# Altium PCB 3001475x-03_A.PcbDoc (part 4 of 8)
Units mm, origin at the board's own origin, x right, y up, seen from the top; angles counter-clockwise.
Board outline 100 x 72 mm, 12 copper layers (Top Layer, L2 GND, Layer 3, L4 GND, Layer 5, L6 PWR, L7 3V3, Layer 8, L9 GND, Layer 10, L11 GND, Bottom Layer), stack 1.735 mm thick; 428 components, 499 nets, 1973 pads, 1473 vias.
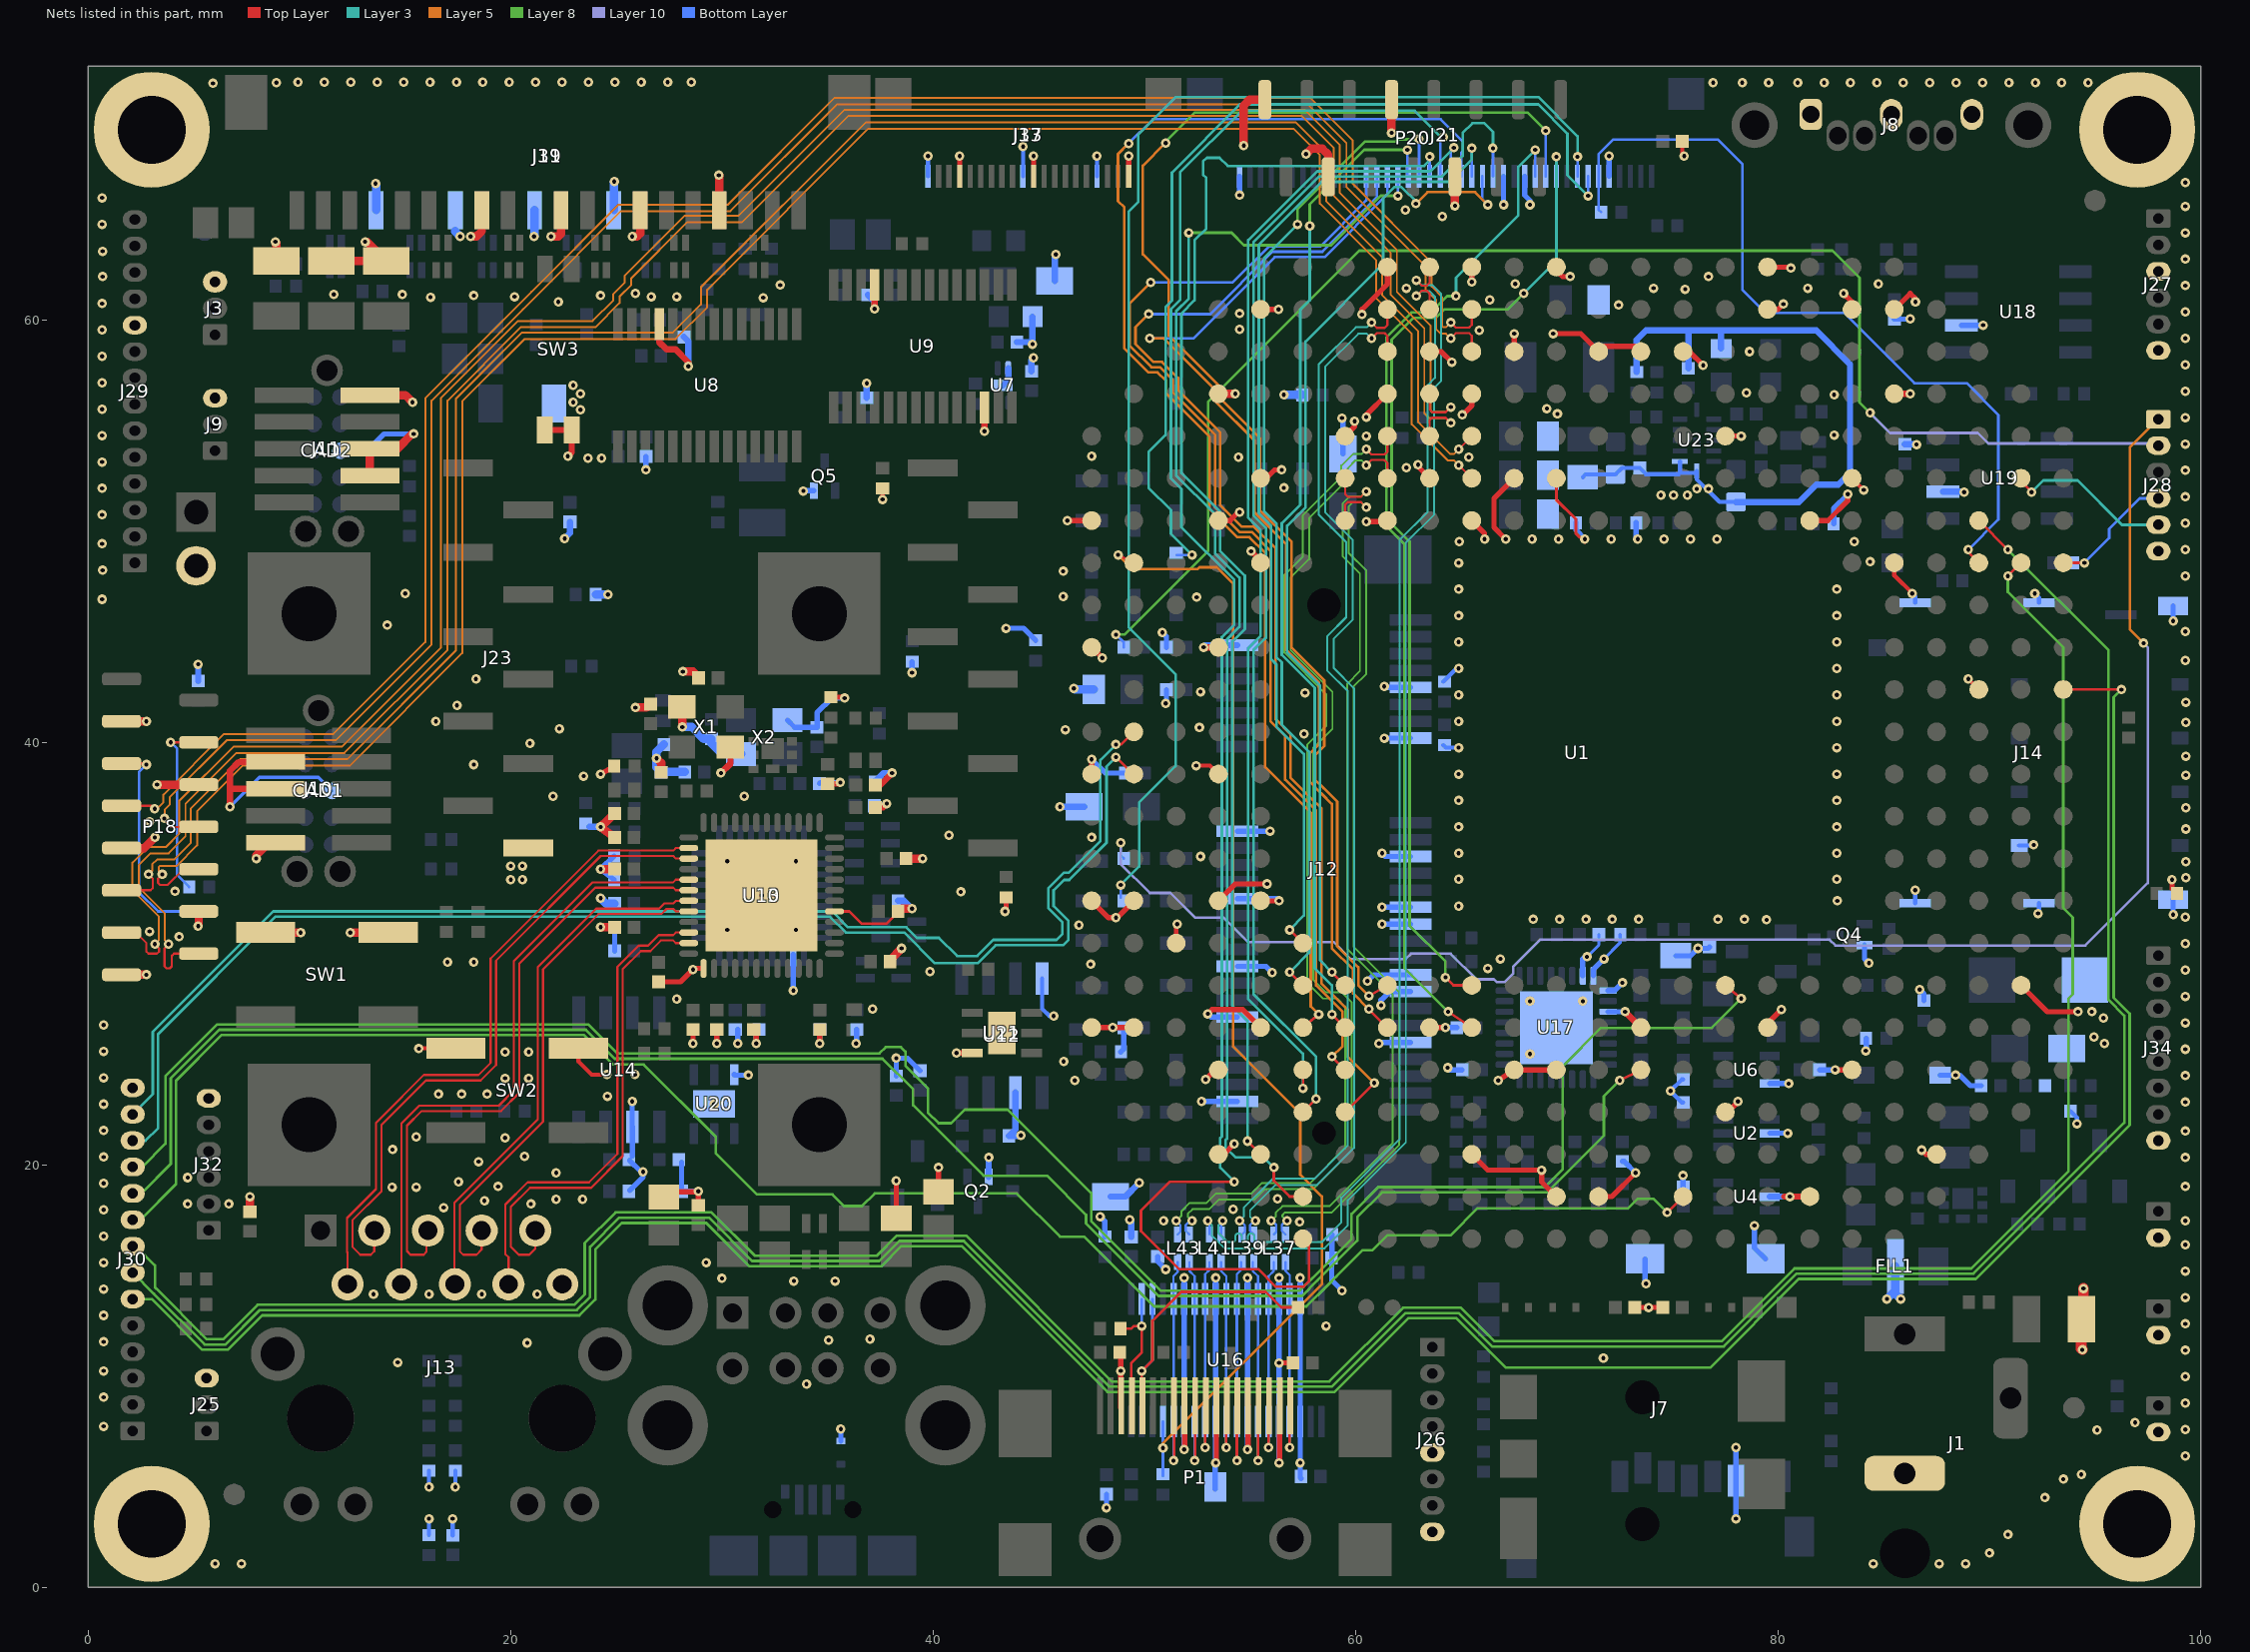
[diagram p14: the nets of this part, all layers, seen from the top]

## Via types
v1: diameter 0.45, hole 0.2, Top Layer to Bottom Layer, 1473 vias

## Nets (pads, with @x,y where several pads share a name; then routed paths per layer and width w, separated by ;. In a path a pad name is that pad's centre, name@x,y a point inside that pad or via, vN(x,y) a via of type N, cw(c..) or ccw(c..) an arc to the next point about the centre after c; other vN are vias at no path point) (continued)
DISP0_DAT11: J21.13 U1.Y7 | length 55.9
  Top Layer w0.125: v1(58.875,25.125) U1.Y7@59.5,24.5
  Layer 5 w0.125: v1(50.3,61.775) 49.3,60.775 49.3,59.454 49.3,58.785 50.322,57.763 50.728,57.763 51.337,57.153 51.337,56.57 53.337,54.57 53.337,51.126 54.501,49.963 55.074,49.963 55.963,49.074 55.963,40.996 56.663,40.296 56.663,38.236 58.061,36.837 58.07,36.837 58.125,36.782 58.125,28.5 59.375,27.25 59.375,25.625 v1(58.875,25.125)
  Bottom Layer w0.125: v1(50.3,61.775) 54.175,61.775 55.875,63.475 58.318,63.475 60.5,65.657 J21.13@60.5,66.8
DISP0_DAT12: J21.14 U1.AA7 | length 57.9
  Top Layer w0.125: U1.AA7@59.5,22.5 v1(60.875,23.875)
  Layer 5 w0.125: v1(50.2,60.275) 49.575,59.65 49.575,58.863 50.426,58.013 50.832,58.013 51.587,57.257 51.587,56.673 53.587,54.673 53.587,51.229 54.604,50.213 55.178,50.213 56.213,49.178 56.213,41.099 56.913,40.399 56.913,38.34 58.165,37.087 58.173,37.087 58.375,36.886 58.375,28.604 59.625,27.354 59.625,27.146 59.625,25.125 v1(60.875,23.875)
  Bottom Layer w0.125: v1(50.2,60.275) 53.11,60.275 56.06,63.225 58.421,63.225 61,65.804 J21.14@61,66.8
DISP0_DAT13: J21.15 U1.W8 | length 53
  Top Layer w0.125: v1(60.625,27.375) U1.W8@61.5,26.5
  Layer 5 w0.125: v1(50.25,59.125) 50.925,59.125 53.387,56.663 53.387,56.122 55.212,54.297 55.212,50.885 56.713,49.385 56.713,44.38 58.263,42.83 58.263,39.928 57.837,39.503 57.837,38.122 58.372,37.587 58.38,37.587 58.875,37.093 58.875,30.25 59.875,29.25 59.875,28.125 v1(60.625,27.375)
  Bottom Layer w0.125: v1(50.25,59.125) 52.313,59.125 56.163,62.975 58.525,62.975 61.5,65.95 J21.15@61.5,66.8
DISP0_DAT14: J21.16 U1.AC6 | length 62.1
  Top Layer w0.125: v1(56.125,19.875) 56.125,19.25 56.875,18.5 U1.AC6@57.5,18.5
  Layer 8 w0.125: v1@52.05,64.125 v1(52.1,64.125) 54.125,64.125 54.713,63.537 58.841,63.537 61.179,65.875 v1(62,65.875)
  Layer 3 w0.125: v1(52.1,64.125) 52.1,61.004 51.5,60.404 51.5,52.646 53.337,50.809 53.337,48.952 54.5,47.789 54.5,45.468 53.913,44.88 53.913,21.246 53.837,21.171 53.837,20.829 54.317,20.35 55.65,20.35 v1(56.125,19.875)
  Bottom Layer w0.125: v1(62,65.875) J21.16@62,66.8
DISP0_DAT15: J21.17 U1.W7 | length 47.7
  Top Layer w0.125: v1(58.875,27.125) U1.W7@59.5,26.5
  Layer 8 w0.125: v1(57.825,64.45) 57.825,65.475 60.4,68.05 v1(62.45,68.05)
  Layer 3 w0.125: v1(57.825,64.45) 57.825,60.925 57.375,60.475 57.375,51.25 56.5,50.375 56.5,44.146 58.063,42.584 58.063,29.312 58.875,28.5 v1(58.875,27.125)
  Bottom Layer w0.125: v1(62.45,68.05) 62.45,66.85 J21.17@62.5,66.8
DISP0_DAT16: J21.18 U1.V6 | length 47.8
  Top Layer w0.125: v1(56.875,29.125) U1.V6@57.5,28.5
  Layer 8 w0.125: v1(57.25,64.525) 57.25,65.254 60.434,68.437 61.871,68.437 61.983,68.55 v1(63,68.55)
  Layer 3 w0.125: v1(56.875,29.125) 57.8,30.05 57.8,39.55 56.5,40.85 56.5,43.793 56.25,44.043 56.25,50.357 55.663,50.945 55.663,62.938 v1(57.25,64.525)
  Bottom Layer w0.125: J21.18@63,66.8 v1(63,68.55)
DISP0_DAT17: J21.19 U1.AB5 | length 61.6
  Top Layer w0.125: v1(54.875,21.125) U1.AB5@55.5,20.5
  Layer 3 w0.125: v1(54.875,21.125) 54.875,26.825 54.163,27.537 54.163,44.777 54.75,45.364 54.75,47.893 53.587,49.055 53.587,50.913 51.75,52.75 51.75,60.3 52.375,60.925 52.375,63.775 52.925,64.325 52.925,66.725 52.775,66.875 52.775,67.498 52.952,67.675 53.55,67.675 53.937,67.288 63.238,67.288 v1@63.5,67.55
  Bottom Layer w0.125: J21.19@63.5,66.8 v1(63.5,67.725)
DISP0_DAT18: J21.20 U1.AD6 | length 83.1
  Top Layer w0.125: v1(54.25,19.2) 51.2,19.2 49.837,17.837 49.837,16.863 51.637,15.063 55.379,15.063 56.204,14.237 57.546,14.237 57.788,14.479 57.788,16.212 U1.AD6@57.5,16.5
  Layer 3 w0.125: v1(54.25,19.2) 53.587,19.863 53.587,21.274 53.663,21.349 53.663,44.984 54.25,45.571 54.25,47.686 51.75,50.186 51.75,52 51.25,52.5 51.25,60.507 51.688,60.945 51.688,66.988 54.6,69.9 62.8,69.9 64.05,68.65 v1(64.15,68.65)
  Bottom Layer w0.125: J21.20@64,66.8 64,68.5 v1(64.15,68.65)
DISP0_DAT19: J21.21 U1.Y6 | length 55.5
  Top Layer w0.125: v1(57.5,23.625) U1.Y6@57.5,24.5
  Layer 3 w0.125: v1(57.5,23.625) 57.5,25.261 54.913,27.848 54.913,44.466 55.5,45.054 55.5,50.046 54.913,50.634 54.913,63.77 58.18,67.038 63.538,67.038 v1(64.65,68.15)
  Bottom Layer w0.125: J21.21@64.5,66.8 64.5,68 v1(64.65,68.15)
DISP0_DAT20: J21.22 U1.W6 | length 65.3
  Top Layer w0.125: U1.W6@57.5,26.5 v1(58.25,27.125)
  Layer 5 w0.125: v1(49.25,68.35) 48.75,67.85 48.75,65.625 49.05,65.325 49.05,58.65 50.187,57.513 50.624,57.513 51.013,57.124 51.013,56.541 53.087,54.466 53.087,51.022 54.397,49.713 54.971,49.713 55.713,48.971 55.713,38.833 57.875,36.67 57.875,27.5 v1(58.25,27.125)
  Bottom Layer w0.125: v1(49.25,68.35) 50.4,69.5 64.025,69.5 65.063,68.462 65.063,67.979 65,67.917 65,67.725 J21.22@65,66.8
DISP0_DAT21: J21.23 U1.U6 | length 48.1
  Top Layer w0.125: v1(56.875,31.125) U1.U6@57.5,30.5
  Layer 3 w0.125: v1(56.875,31.125) 57.55,31.8 57.55,39.446 56.25,40.746 56.25,43.689 56,43.939 56,50.254 55.413,50.841 55.413,63.563 58.388,66.538 64.438,66.538 65.5,67.6 v1(65.5,68.125)
  Bottom Layer w0.125: J21.23@65.5,66.8 v1(65.5,68.125)
DISP0_DAT22: J21.24 U1.V7 | length 47.8
  Top Layer w0.125: v1(58.875,29.125) U1.V7@59.5,28.5
  Layer 5 w0.125: v1(62.85,65.5) 63.4,66.05 65.65,66.05 v1(66.25,65.45)
  Layer 3 w0.125: v1(58.875,29.125) 58.313,29.687 58.313,42.687 56.75,44.25 56.75,50.25 57.625,51.125 57.625,58.975 61.3,62.65 61.3,65.758 61.829,66.288 62.171,66.288 62.85,65.608 v1(62.85,65.5)
  Bottom Layer w0.125: J21.24@66,66.8 66,65.7 v1(66.25,65.45)
DISP0_DAT23: J21.25 U1.AA6 | length 59.7
  Top Layer w0.125: U1.AA6@57.5,22.5 v1(58.125,23.125)
  Layer 3 w0.125: v1(58.125,23.125) 58.125,25.125 55.163,28.087 55.163,44.363 55.75,44.95 55.75,50.15 55.163,50.737 55.163,63.666 58.284,66.788 64.088,66.788 65.063,67.763 65.063,68.846 65.529,69.313 66.087,69.313 66.5,68.9 v1(66.5,68.125)
  Bottom Layer w0.125: J21.25@66.5,66.8 v1(66.5,68.125)
DISP0_DRDY: J21.31 U1.V10 | length 47.8
  Top Layer w0.125: v1(64.25,28.875) 64.625,28.5 U1.V10@65.5,28.5
  Layer 8 w0.125: v1(64.25,28.875) 64.25,29.625 62.55,31.325 62.55,49.5 61.7,50.35 61.7,59.058 62.742,60.1 63.8,60.1 64.2,60.5 67.2,60.5 v1(67.95,61.25)
  Layer 3 w0.125: v1(67.95,61.25) 69.5,62.8 v1(69.5,67.725)
  Bottom Layer w0.125: J21.31@69.5,66.8 v1(69.5,67.725)
DISP0_HSYNC: J21.29 U1.W10 | length 48.3
  Top Layer w0.125: v1(64.375,27.25) U1.W10@65.5,26.5
  Layer 8 w0.125: v1(64.375,27.25) 62.3,29.325 62.3,49.396 61.45,50.246 61.45,59.162 62.638,60.35 63.55,60.35 64.325,61.125 v1(64.75,61.125)
  Layer 3 w0.125: v1(64.75,61.125) 64.75,62 67.7,64.95 67.7,67.25 v1(68.5,68.05)
  Bottom Layer w0.125: J21.29@68.5,66.8 v1(68.5,68.05)
DISP0_I2C_SCL: J21.33 R103.2 | length 62.5
  Layer 3 w0.125: v1(48.875,33.25) 49.75,34.125 49.75,37.15 51.475,38.875 51.475,43.225 49.25,45.45 49.25,65.125 49.7,65.575 49.7,68.75 51.5,70.55 68.646,70.55 70.5,68.696 v1(70.5,67.725)
  Bottom Layer w0.125: R103.2@48.875,32.645 v1(48.875,33.25) ; J21.33@70.5,66.8 v1(70.5,67.725)
DISP0_I2C_SDA: J21.34 R105.2 | length 45
  Layer 3 w0.125: v1(52.25,48.875) 51.25,49.875 51.25,51 50.2,52.05 50.2,53.75 51,54.55 51,60.611 51.298,60.909 51.298,66.973 54.525,70.2 68.643,70.2 70.025,68.818 70.025,66.85 v1(71,65.875)
  Bottom Layer w0.125: R105.2@51.52,48.875 v1(52.25,48.875) ; v1(71,65.875) J21.34@71,66.8
DISP0_IRQ_N: J21.35 R78.2 U1.H22 | length 38.7
  Top Layer w0.125: v1(89,49.125) 89,49 U1.H22@89.5,48.5
  Bottom Layer w0.125: R78.2@71.62,65.1 71.5,65.22 J21.35@71.5,66.8 71.5,67.833 72.204,68.538 77.143,68.538 78.315,67.366 78.315,61.413 79.391,60.337 83.113,60.337 86.45,57 88.925,57 90.425,55.5 90.425,50.55 v1(89,49.125)
DISP0_VSYNC: J21.30 U1.V8 | length 67.7
  Top Layer w0.125: v1(60.625,28) U1.V8@61.5,28.5
  Layer 8 w0.125: v1@51,68.425 52.388,69.813 68.137,69.813 v1(69,68.95)
  Layer 5 w0.125: v1(51,68.375) 49.925,67.3 49.925,63.1 51.15,61.875 51.15,59.254 53.637,56.766 53.637,56.226 55.462,54.401 55.462,50.989 56.963,49.489 56.963,44.484 58.513,42.934 58.513,39.824 58.087,39.399 58.087,38.226 58.476,37.837 58.484,37.837 59.125,37.196 59.125,30.354 60.125,29.354 60.125,29.146 60.125,28.5 v1(60.625,28)
  Bottom Layer w0.125: J21.30@69,66.8 v1(69,68.95)
DSI_CLK0_N: P18.11 U1.E10 | length 100
  Top Layer w0.104: P18.11@1.575,33 2.95,33 3.048,33.098 3.048,33.553 v1(2.851,33.75) ; v1(64.875,53.875) U1.E10@65.5,54.5
  Layer 5 w0.093: v1(2.851,33.75) 3.026,33.925 3.026,34.224 3.251,34.45 4.05,34.45 4.85,35.25 4.85,36.874 7.176,39.2 12.25,39.2 17.4,44.35 17.4,56.262 20.538,59.4 27.675,59.4 29,60.725 29,61.55 36.8,69.35 57.174,69.35 58.6,67.924 58.6,65.624 61.263,62.961 61.263,61.161 62.95,59.474 62.95,59.316 62.951,58.735 62.95,55.174 64.474,53.65 64.65,53.65 v1(64.875,53.875)
DSI_CLK0_P: P18.10 U1.F10 | length 100
  Top Layer w0.104: v1(3.5,33.75) 3.303,33.553 3.303,33.347 3.4,33.25 3.75,33.25 4.5,34 P18.10@5.225,34 ; v1(64.875,53.125) U1.F10@65.5,52.5
  Layer 5 w0.093: v1(3.5,33.75) 3.326,33.925 3.326,34.1 3.375,34.15 4.174,34.15 5.15,35.126 5.15,36.75 7.3,38.9 12.374,38.9 17.7,44.226 17.7,56.138 20.662,59.1 27.799,59.1 29.3,60.601 29.3,61.426 36.924,69.05 57.05,69.05 58.3,67.8 58.3,65.5 60.963,62.837 60.963,61.037 62.65,59.35 62.65,59.191 62.651,58.859 ; 62.65,58.859 62.65,55.05 64.35,53.35 64.65,53.35 v1(64.875,53.125)
DSI_D0_N: P18.8 U1.C10 | length 93.1
  Top Layer w0.104: v1(3.6,36.4) 3.6,36.3 3.9,36 P18.8@5.225,36 ; v1(64.5,59.125) 64.744,59.369 65.381,59.369 65.5,59.25 U1.C10@65.5,58.5
  Layer 5 w0.093: v1(3.6,36.4) 3.616,36.416 3.616,36.813 3.85,37.048 3.85,37.4 6.55,40.1 11.724,40.1 16.25,44.626 16.25,56.176 20.573,60.499 21.101,61.027 25.224,65.15 30.4,65.15 35.462,70.212 57.714,70.212 59.562,68.364 59.562,66.288 63.3,62.55 63.3,61.45 63.8,60.95 63.8,59.576 64.026,59.35 64.275,59.35 v1(64.5,59.125)
DSI_D0_P: P18.7 U1.B10 | length 93.1
  Top Layer w0.104: P18.7@1.575,37 3,37 v1(3.141,36.859) ; v1(64.5,59.875) 64.744,59.631 65.365,59.631 65.5,59.766 U1.B10@65.5,60.5
  Layer 5 w0.093: v1(3.141,36.859) 3.157,36.875 3.316,36.875 3.316,36.938 3.55,37.172 3.55,37.524 6.426,40.4 11.6,40.4 15.95,44.75 15.95,56.3 20.273,60.623 20.977,61.327 25.1,65.45 30.276,65.45 35.338,70.512 57.838,70.512 59.862,68.488 59.862,66.443 63.6,62.705 63.6,61.574 64.1,61.074 64.1,59.7 64.15,59.65 64.275,59.65 v1(64.5,59.875)
DSI_D1_N: P18.14 U1.E9 | length 105.5
  Top Layer w0.104: v1(3.799,30.45) 3.602,30.253 3.602,29.398 3.7,29.3 3.85,29.3 3.95,29.4 3.95,29.9 4.05,30 4.3,30 P18.14@5.225,30 ; U1.E9@63.5,54.5 63.5,55.25 63.619,55.369 64.256,55.369 v1(64.5,55.125)
  Layer 5 w0.093: v1(3.799,30.45) 3.625,30.625 3.625,31.9 2.388,33.136 2.388,34.188 2.95,34.75 3.55,34.75 3.799,34.75 4.6,35.551 4.6,37.1 7,39.5 12.124,39.5 17,44.376 17,56.182 20.468,59.65 24,59.65 25.15,60.8 25.15,61.1 25.7,61.65 25.7,61.976 28.348,64.624 30.949,64.624 35.975,69.65 57.45,69.65 58.95,68.15 58.95,65.884 61.65,63.184 61.65,61.2 63.25,59.6 63.25,55.576 63.476,55.35 64.275,55.35 v1(64.5,55.125)
DSI_D1_P: P18.13 U1.D9 | length 105.5
  Top Layer w0.104: P18.13@1.575,31 2.25,31 2.75,30.5 2.75,30.1 2.85,30 3.247,30 3.347,30.1 3.347,30.253 v1(3.15,30.45) ; U1.D9@63.5,56.5 63.5,55.766 63.635,55.631 64.256,55.631 v1(64.5,55.875)
  Layer 5 w0.093: v1(3.15,30.45) 3.325,30.625 3.325,31.775 2.088,33.012 2.088,34.312 2.826,35.05 3.674,35.05 4.3,35.676 4.3,37.224 6.876,39.8 12,39.8 16.7,44.5 16.7,56.306 20.344,59.95 23.876,59.95 24.85,60.924 24.85,61.224 25.4,61.774 25.4,62.1 28.224,64.924 30.774,64.924 35.8,69.95 57.574,69.95 59.25,68.274 59.25,66.008 61.95,63.308 61.95,61.324 63.55,59.724 63.55,55.7 63.6,55.65 64.275,55.65 v1(64.5,55.875)
DSI_I2C_SCL: P18.5 R155.2 | length 10.1
  Top Layer w0.125: P18.5@1.575,39 2.7,39 v1(2.75,38.95)
  Bottom Layer w0.125: v1(2.75,38.95) 2.4,38.6 2.4,32.9 3.3,32 R155.2@4.745,32
DSI_I2C_SDA: P18.4 R156.2 | length 8.5
  Top Layer w0.125: v1(3.9,40) P18.4@5.225,40
  Bottom Layer w0.125: v1(3.9,40) 4.2,39.7 4.2,33.72 R156.2@4.77,33.15
ETH_TXRXA_N: J13.3 U10.3 | length 31.3
  Top Layer w0.104: J13.3@13.54,16.89 13.54,15.915 13.375,15.75 12.875,15.75 12.5,16.125 12.5,17.375 13.875,18.75 13.875,21.889 15.986,24.001 18.576,24.001 19.3,24.725 19.3,29.664 24.258,34.622 27.689,34.622 27.811,34.5 U10.3@28.425,34.5
ETH_TXRXA_P: J13.2 U10.2 | length 31.3
  Top Layer w0.104: J13.2@12.27,14.35 12.27,15.855 12.245,15.88 12.245,17.481 13.62,18.856 13.62,21.995 13.907,22.282 15.881,24.256 18.47,24.256 19.045,24.831 19.045,29.77 24.152,34.877 27.689,34.877 27.811,35 U10.2@28.425,35
ETH_TXRXB_N: J13.5 U10.6 | length 29.6
  Top Layer w0.104: J13.5@16,16.81 16,15.875 15.875,15.75 15.25,15.75 15.08,15.92 15.08,21.855 15.775,22.55 19.536,22.55 20.4,23.414 20.4,29.525 23.997,33.122 27.689,33.122 27.811,33 U10.6@28.425,33
ETH_TXRXB_P: J13.4 U10.5 | length 29.6
  Top Layer w0.104: J13.4@14.825,14.365 14.825,21.961 15.669,22.805 19.43,22.805 20.145,23.52 20.145,29.645 23.877,33.377 27.689,33.377 27.811,33.5 U10.5@28.425,33.5
ETH_TXRXC_N: J13.7 U10.8 | length 25.2
  Top Layer w0.104: J13.7@18.62,16.89 18.62,15.995 18.375,15.75 17.75,15.75 17.583,15.917 17.583,18.097 21.53,22.044 21.53,29.255 24.15,31.875 27.128,31.875 27.375,32.123 27.689,32.123 27.811,32 U10.8@28.425,32
ETH_TXRXC_P: J13.6 U10.7 | length 25.2
  Top Layer w0.104: U10.7@28.425,32.5 27.811,32.5 27.689,32.378 27.269,32.378 27.022,32.13 24.23,32.13 24.044,32.13 21.275,29.361 21.275,22.15 17.328,18.203 J13.6@17.328,14.372 ; J13.6@17.328,14.372 J13.6@17.35,14.35 ; J13.6@17.328,14.372 J13.6@17.35,14.35 ; J13.6@17.35,14.35 17.375,14.375 J13.6@17.35,14.35
ETH_TXRXD_N: J13.9 U10.11 | length 23.1
  Top Layer w0.104: J13.9@21.16,16.89 21.16,16.035 20.875,15.75 20.375,15.75 20,16.125 20,18.014 20.905,18.92 23.805,18.92 25.3,20.414 25.3,29.269 26.156,30.125 26.611,30.125 27.108,30.622 27.689,30.622 27.811,30.5 U10.11@28.425,30.5
ETH_TXRXD_P: J13.8 U10.10 | length 23
  Top Layer w0.104: J13.8@19.89,14.35 19.89,15.624 19.745,15.769 19.745,18.12 20.8,19.175 23.7,19.175 25.045,20.52 25.045,29.375 25.05,29.38 26.05,30.38 26.505,30.38 27.002,30.877 27.689,30.877 27.811,31 U10.10@28.425,31
EXP_GPIO_0: J30.6 U1.L24 | length 134.5
  Top Layer w0.125: U1.L24@93.5,42.5 v1(96.25,42.5)
  Layer 8 w0.125: J30.6@2.1,13.65 3,13.65 5.4,11.25 6.6,11.25 8.225,12.875 23.25,12.875 24,13.625 24,16 25.25,17.25 29.25,17.25 29.3,17.2 29.304,17.2 31.304,15.2 37.546,15.2 38.496,16.15 41.343,16.15 48.243,9.25 48.729,9.25 59,9.25 62.487,12.737 64.77,12.737 67.107,10.4 76.775,10.4 80.975,14.6 89.35,14.6 96.64,21.89 96.64,27.164 95.887,27.916 95.887,42.137 v1(96.25,42.5)
EXP_GPIO_1: J30.7 U1.G22 | length 141.5
  Top Layer w0.125: U1.G22@89.5,50.5 v1(90.875,49.125)
  Layer 8 w0.125: J30.7@2.1,14.9 3.1,13.9 3.104,13.9 5.504,11.5 6.496,11.5 8.121,13.125 23.125,13.125 23.75,13.75 23.75,16.125 25.125,17.5 29.375,17.5 31.425,15.45 37.443,15.45 38.393,16.4 41.446,16.4 48.346,9.5 58.875,9.5 62.362,12.987 64.873,12.987 66.461,11.4 77.421,11.4 80.871,14.85 89.246,14.85 96.39,21.993 96.39,27.06 95.637,27.813 95.637,44.363 v1(90.875,49.125)
EXP_GPIO_2: J30.8 U1.H23 | length 137.9
  Top Layer w0.125: v1(90.875,47.875) U1.H23@91.5,48.5
  Layer 8 w0.125: J30.8@2.1,16.15 2.25,16.15 3.15,15.25 3.15,14.204 3.204,14.15 3.207,14.15 5.607,11.75 6.393,11.75 8.018,13.375 23,13.375 23.5,13.875 23.5,16.293 24.957,17.75 29.5,17.75 31.55,15.7 37.325,15.7 38.275,16.65 41.55,16.65 48.45,9.75 58.75,9.75 62.237,13.237 64.977,13.237 66.564,11.65 77.318,11.65 80.768,15.1 89.143,15.1 93.737,19.695 93.737,27.862 93.95,28.075 93.95,31.717 93.5,32.167 93.5,44.5 90.875,47.125 v1(90.875,47.875)
EXP_GPIO_3: J30.9 U1.AC15 | length 88.9
  Top Layer w0.125: v1(74.75,17.75) U1.AC15@75.5,18.5
  Layer 8 w0.125: J30.9@2.1,17.4 2.45,17.4 4.15,19.1 4.15,23.993 6.307,26.15 23.45,26.15 24.85,24.75 26.3,24.75 29.7,21.35 29.7,20.55 31.65,18.6 35.23,18.6 35.78,18.05 36.625,18.05 37.225,18.65 43.954,18.65 46.004,16.6 47.15,16.6 50.45,13.3 51.039,13.3 57.669,13.3 58.687,14.318 58.687,14.324 59.076,14.713 59.082,14.713 60.332,15.962 60.796,15.962 61.508,16.675 64.504,16.675 65.779,17.95 72.904,17.95 73.354,18.4 74.1,18.4 v1(74.75,17.75)
EXP_GPIO_4: J30.10 U1.Y14 | length 89
  Top Layer w0.125: v1(72.5,24) U1.Y14@73.5,24.5
  Layer 8 w0.125: J30.10@2.1,18.65 2.5,18.65 3.9,20.05 3.9,24.096 6.204,26.4 23.554,26.4 24.929,25.025 37.6,25.025 39.05,23.575 39.05,22.825 42.388,19.487 45.388,19.487 47.237,17.638 47.237,17.226 50.663,13.8 57.462,13.8 58.187,14.526 58.187,14.532 58.868,15.213 58.874,15.213 60.075,16.413 60.075,17.533 61.242,18.7 69.054,18.7 71.75,21.396 71.75,23.25 v1(72.5,24)
EXP_GPIO_5: J30.11 U1.V16 | length 98.9
  Top Layer w0.125: U1.V16@77.5,28.5 v1(78.25,27.875)
  Layer 8 w0.125: J30.11@2.1,19.9 2.55,19.9 3.65,21 3.65,24.2 6.1,26.65 23.657,26.65 25.032,25.275 37.45,25.275 37.75,25.575 38.475,25.575 38.685,25.365 38.685,24.69 39.75,23.625 39.75,22.479 40.25,21.979 40.854,21.979 41.488,22.613 43.521,22.613 47.487,18.646 47.487,17.329 50.767,14.05 57.358,14.05 57.937,14.629 57.937,14.635 58.765,15.463 58.771,15.463 59.8,16.492 59.8,17.675 61.075,18.95 68.95,18.95 69.8,19.8 69.8,24.675 71.612,26.487 76.862,26.487 v1(78.25,27.875)
EXP_GPIO_6: J30.12 U1.N2 | length 64.2
  Top Layer w0.125: v1(48.65,39.3) 49.45,38.5 U1.N2@49.5,38.5
  Layer 3 w0.125: J30.12@2.1,21.15 2.7,21.15 3.3,21.75 3.3,26.196 8.854,31.75 35.113,31.75 35.863,31 38.625,31 40.075,29.55 42.1,29.55 42.95,30.4 46.154,30.4 46.4,30.646 46.4,31.55 45.7,32.25 45.7,32.996 46.191,33.488 46.438,33.488 48.2,35.25 48.2,38.85 v1(48.65,39.3)
EXP_GPIO_7: J30.13 U1.M2 | length 62.8
  Top Layer w0.125: v1(48.65,39.9) 48.9,39.9 U1.M2@49.5,40.5
  Layer 3 w0.125: J30.13@2.1,22.4 3.05,23.35 3.05,26.3 8.75,32 35.216,32 35.966,31.25 38.729,31.25 39.229,30.75 40.267,30.75 41.129,29.887 42.084,29.887 42.846,30.65 45.833,30.65 46.113,30.929 46.113,31.484 45.45,32.146 45.45,33.1 46.187,33.837 46.421,33.837 47.913,35.329 47.913,39.163 v1(48.65,39.9)
EXP_I2C_GPIO: J28.5 U1.F23 | length 8
  Top Layer w0.125: U1.F23@91.5,52.5 91.5,52.35 v1(92,51.85)
  Layer 3 w0.125: v1(92,51.85) 92.55,52.4 94.175,52.4 96.275,50.3 J28.5@98,50.3
EXP_I2C_IRQ_N: J28.4 R117.2 U1.H24 | length 6.5
  Top Layer w0.125: U1.H24@93.5,48.5 v1(94.5,48.5)
  Bottom Layer w0.125: R117.2@93.98,48.5 v1(94.5,48.5) 95.675,49.675 95.675,50.1 97.125,51.55 J28.4@98,51.55
EXP_I2C_SCL: J28.1 R106.2 | length 78.2
  Layer 5 w0.125: v1(97.3,44.7) 96.65,45.35 96.65,53.95 J28.1@98,55.3
  Layer 10 w0.125: v1(48.875,35.25) 48.875,34.25 50.25,32.875 51.225,32.875 52.4,31.7 53.75,31.7 54.9,30.55 58.95,30.55 59.75,29.75 62.375,29.75 62.625,30 64.5,30 65.713,28.788 66.546,28.788 66.683,28.65 67.05,28.65 67.45,29.05 67.45,29.383 68.729,30.663 82.437,30.663 82.713,30.387 94.537,30.387 97.5,33.35 97.5,44.5 v1(97.3,44.7)
  Bottom Layer w0.125: v1(48.875,35.25) 48.875,34.645 R106.2@49.02,34.5
EXP_I2C_SDA: J28.2 R107.2 | length 69
  Layer 8 w0.125: v1(48.65,45.1) 49.058,45.1 53.012,49.054 53.012,56.112 60.174,63.274 82.576,63.274 83.85,62 83.85,56.1 v1(84.35,55.6)
  Layer 10 w0.125: v1(84.35,55.6) 85.3,54.65 89.45,54.65 89.95,54.15 97.9,54.15 J28.2@98,54.05
  Bottom Layer w0.125: v1(48.65,45.1) 49.02,44.73 R107.2@49.02,44.5
GND: C1.2 C2.1 C3.1 C4.1 C5.1 C6.1 C7.1 C8.1 C9.2 C10.1 C11.1 C12.1 C13.1 C24.1 C25.1 C26.1 C27.1 C28.1 C29.1 C30.1 C33.2 C34.2 C35.2 C36.2 C37.1 C38.1 C39.1 C40.1 C41.1 C42.1 C43.1 C44.1 C45.1 C46.1 C47.1 C48.1 C49.1 C50.1 C51.1 C52.1 C53.1 C54.1 C55.1 C56.1 C57.1 C58.1 C59.1 C60.1 C61.1 C62.1 C63.2 C64.2 C65.2 C66.1 C67.1 C68.1 C69.1 C70.1 C71.1 C72.1 C73.1 C74.1 C75.1 C76.1 C77.1 C78.1 C79.1 C80.1 C81.1 C82.1 C83.1 C84.1 C85.1 C86.1 C89.1 C90.1 C95.1 C96.1 C99.1 C100.1 C101.1 C105.1 C106.1 C109.1 C110.1 C111.1 C112.1 C113.1 C114.1 C115.1 C116.1 C117.1 C118.1 C119.1 CAD1.3 CAD2.3 D1.K D2.A D4.K D5.K D6.K D10.1 FIL1.2 J1.2 J2.2 J3.3 J4.2 J5.2 J7.6 J7.9 J7.10 J8.1 J8.4 J8.7 J9.3 J10.3 J10.5 J10.9 J11.3 J11.5 J11.9 J12.4 J12.9 J12.15 J12.18 J12.21 J12.26 J12.27 J12.29 J12.34 J12.35 J12.37 J12.40 J12.43 J12.50 J13.10 J14.5 J14.11 J14.12 J14.13 J14.14 J14.15 J14.16 J17.1 J17.10 J17.17 J18.2 J19.4 J19.7 J19.10 J19.13 J21.1 J21.26 J21.28 J21.36 J23.10 J25.3 J26.5 J26.8 J27.3 J27.6 J28.6 J29.10 J30.14 J31.4 J31.7 J31.10 J31.13 J32.6 J33.1 J33.10 J33.17 J34.8 L12.1 L13.1 L15.1 L27.1 P1.2 P1.5 P1.8 P1.11 P1.17 P18.3 P18.6 P18.9 P18.12 P18.15 P20.6 P20.9 P20.12 P20.15 pad.0@3,3 pad.0@3,69 pad.0@97,3 pad.0@97,69 Q2.S Q4.S Q5.S R5.1 R14.1 R17.2 R18.2 R19.2 R20.1 R27.1 R28.2 R29.2 R37.1 R42.1 R43.1 R46.1 R49.1 R50.1 R54.2 R56.2 R57.2 R59.2 R70.1 R71.1 R73.1 R74.1 R84.1 R89.1 R130.2 R134.2 R136.2 R138.1 R144.1 R145.1 R146.1 SW1.1 SW1.2 SW2.1 SW2.2 SW3.1 SW3.2 U1.A8 U1.A10 U1.A12 U1.A17 U1.AA16 U1.AB4 U1.AB10 U1.AB21 U1.AC12 U1.AC13 U1.AC18 U1.B5 U1.B17 U1.B19 U1.B20 U1.C9 U1.C11 U1.C13 U1.C14 U1.C15 U1.D4 U1.D8 U1.D10 U1.D20 U1.E7 U1.E16 U1.F5 U1.F9 U1.F11 U1.F12 U1.F19 U1.G1 U1.G4 U1.G8 U1.G10 U1.G18 U1.H5 U1.H20 U1.K1 U1.K4 U1.L22 U1.N1 U1.N4 U1.T1 U1.T2 U1.T4 U1.T5 U1.U3 U1.V23 U1.W1 U1.W2 U1.W5 U1.W9 U1.W14 U1.W17 U1.Y4 U1.Y11 U1.Y12 U1.Y19 U2.2 U4.2 U5.A U6.3 U7.2 U7.5 U8.25 U9.12 U9.25 U10.13 U10.29 U10.49 U12.4 U12.6 U13.11 U13.37 U14.6 U16.3 U16.5 U16.8 U16.11 U16.14 U16.25 U16.28 U16.31 U16.34 U16.36 U17.1 U17.3 U17.31 U17.32 U17.33 U18.2 U19.2 U20.3 U20.7 U21.3 U21.7 U23.1 U23.12 X1.2 X1.4 X2.2 X2.4 | length 425.4
  Top Layer w0.125: U10.29@35.325,32 36.021,32 36.609,31.413 37.788,31.413 C54.1@38.5,32.125
  Top Layer w0.15: U1.F12@69.5,52.5 69.5,51.5 70.42,50.58 70.42,49.905 v1@70.85,49.475
  Top Layer w0.2: v1(15.65,25.5) 15.675,25.525 SW2.1@17.4,25.525 ; SW2.2@23.2,25.525 23.2,24.9 23.825,24.275 v1(24.55,24.275) ; v1(37.6,51.5) R136.2@37.6,52.02 ; U1.U3@51.5,30.5 51.5,31.35 v1(51.55,31.4) ; v1(52.45,38.9) 53.1,38.9 U1.N4@53.5,38.5 ; C106.1@75.46,68.45 75.46,67.84 v1(75.55,67.75) ; U1.F19@83.5,52.5 v1(84.05,51.95) ; U1.H20@85.5,48.5 85.5,47.9 v1(86.35,47.05) ; v1(89,43) U1.L22@89.5,42.5
  Top Layer w0.25: v1(24.25,38.5) R49.1@24.895,38.875 ; R49.1@24.834,38.953 R49.1@24.895,39 ; C43.1@27,28.665 28.04,28.665 v1(28.625,29.25) 28.675,29.3 U10.13@29.125,29.3 ; L15.1@27.25,18.725 v1@28.85,18.725 ; v1(28.625,25.75) C50.1@28.625,26.415 ; C71.1@28.875,18.085 v1@28.875,18.725 ; v1(29.75,25.75) C46.1@29.75,26.415 ; v1(31.625,25.75) C51.1@31.625,26.415 ; v1(34.625,25.75) C52.1@34.625,26.415 ; C47.1@35,38.04 35.54,38.04 v1(35.6,38.1) ; R50.1@35.15,42.14 35.76,42.14 v1(35.8,42.1) ; L13.1@38.25,17.475 v1(38.25,19.25) ; L12.1@40.25,18.725 v1(40.25,19.875) ; v1(41.1,25.3) U21.3@41.85,25.3 ; J17.17@41.25,66.8 v1(41.25,67.75) ; v1(43.4,32) 43.45,32.05 R130.2@43.45,32.67 ; J17.10@44.75,66.8 v1(44.75,67.75) ; v1(46.35,50.5) U1.G1@47.5,50.5 ; U1.W1@47.5,26.5 U1.W2@49.5,26.5 ; U1.T1@47.5,32.5 48.3,31.7 v1(48.65,31.7) 48.7,31.7 U1.T2@49.5,32.5 ; U1.N1@47.5,38.5 v1(47.5,39.2) ; U1.K1@47.5,44.5 v1(48,44) ; P1.17@48.875,8.5 v1(48.875,10.25) C86.1@48.875,11.085 ; J17.1@49.25,66.8 v1(49.25,67.75) ; v1(51.875,6.525) 51.9,6.55 P1.11@51.9,8.6 ; v1(52.9,24.05) 53.35,24.5 U1.Y4@53.5,24.5 ; v1(53,27.15) 53.2,27.35 54.65,27.35 U1.W5@55.5,26.5 ; v1(53.375,5.9) 53.4,5.925 P1.8@53.4,8.6 ; U1.AB4@53.5,20.5 53.75,20.5 v1(54.25,21) ; U1.T4@53.5,32.5 54.3,33.3 v1(55.8,33.3) ; U1.G4@53.5,50.5 54.05,50.5 54.45,50.9 v1(54.5,50.9) ; v1(54.875,6.525) 54.9,6.55 P1.5@54.9,8.6 ; v1(55.05,49.05) 55.5,48.6 U1.H5@55.5,48.5 ; U1.T5@55.5,32.5 v1(56.375,32.5) ; U1.F5@55.5,52.5 55.758,52.5 56.158,52.9 v1(56.5,52.9) ; U1.B5@55.5,60.5 v1(56.35,60.5) ; v1(56.375,5.9) 56.4,5.925 P1.2@56.4,8.6 ; v1(56.375,10.625) C82.1@57.04,10.625 ; U1.E7@59.5,54.5 59.95,54.95 v1(59.95,55.2) ; v1(60.3,60.25) 60.3,60.5 61.5,61.7 U1.A8@61.5,62.5 ; v1(60.5,50.45) 61.45,50.45 U1.G8@61.5,50.5 ; v1(60.5,55.4) 60.5,55.5 U1.D8@61.5,56.5 ; v1(62.95,53.15) 62.95,53.05 U1.F9@63.5,52.5 ; U1.W9@63.5,26.5 v1(64.25,26.5) ; U1.C9@63.5,58.5 64.05,58.5 v1(64.55,58) ; v1(65.05,55.5) 65.5,55.95 U1.D10@65.5,56.5 ; U1.AB10@65.5,20.5 66.25,19.75 v1(68.8,19.75) 68.8,19.2 U1.AC12@69.5,18.5 ; U1.G10@65.5,50.5 66.1,49.9 v1(66.1,49.625) v1@66.1,49.6 ; v1(65.5,61.8) U1.A10@65.5,62.5 ; v1(66.75,24) U1.Y11@67.5,24.5 U1.Y12@69.5,24.5 ; v1(67.1,49.625) 66.55,50.175 66.55,51.55 U1.F11@67.5,52.5 ; U1.C11@67.5,58.5 v1(67.5,59.35) ; v1(69.35,59.35) 70.65,59.35 U1.C13@71.5,58.5 71.75,58.75 73.25,58.75 U1.C14@73.5,58.5 ; U1.A12@69.5,62.5 69.5,62.35 69.8,62.05 v1(70.15,62.05) ; U1.AC13@71.5,18.5 72.125,18.5 v1(73.25,19.625) ; C13.1@73.21,13.25 v1(73.875,13.25) C12.1@74.54,13.25 ; U1.C15@75.5,58.5 75.8,58.5 v1(76.45,57.85) ; U1.AA16@77.5,22.5 77.6,22.5 v1(78.1,23) ; U1.E16@77.5,54.5 v1(78.25,54.5) ; U1.W17@79.5,26.5 79.5,26.7 v1(80.15,27.35) ; U1.B17@79.5,60.5 80,60.5 v1(80.25,60.75) ; U1.A17@79.5,62.5 80.55,62.5 v1(80.6,62.45) ; U1.G18@81.5,50.5 82.35,50.5 83.3,51.45 v1(83.3,51.75) ; v1(82.7,24.5) U1.Y19@83.5,24.5 ; v1(83.1,61.25) 83.5,60.85 U1.B19@83.5,60.5 ; U1.B20@85.5,60.5 86.25,61.25 86.5,61 v1(86.5,60.85) ; v1(86.8,20.7) 87,20.5 U1.AB21@87.5,20.5 ; U1.V23@91.5,28.5 92.75,27.25 v1(94.2,27.25) ; v1(98.65,33.5) 98.65,33.08 R18.2@98.88,32.85
  Top Layer w0.3: v1(6.7,36.95) 6.7,37.8 ; J10.5@8.868,37.8 6.7,37.8 ; J10.3@8.868,39.07 7.12,39.07 6.7,38.65 6.7,37.8 ; SW3.1@21.465,54.79 SW3.1@21.615,54.79 SW3.2@22.885,54.79 22.885,53.735 v1(22.7,53.55) ; U8.25@27.025,59.805 27.025,58.95 27.375,58.6 27.8,58.6 28.4,58 v1(28.4,57.8) ; v1(29.95,38.55) 30.4,39 X1.2@30.4,39.775 ; v1(37.225,60.525) U9.25@37.225,61.65 ; C56.1@37.26,36.925 37.625,36.925 v1(37.8,37.1) ; C55.1@37.26,37.975 37.475,37.975 v1(38.05,38.55) ; v1(42.425,54.725) U9.12@42.425,55.85 ; v1(52.8,44.5) U1.K4@53.5,44.5 ; v1(72.75,27.25) U1.W14@73.5,26.5 ; v1(80.55,18.5) 80.3,18.5 U1.AC18@81.5,18.5 ; U1.D20@85.5,56.5 v1(86.25,56.5)
  Top Layer w0.4: P18.15@1.575,29 v1(2.75,29) ; P18.9@1.575,35 2.65,35 v1(3.15,35.5) ; P18.3@1.575,41 v1(2.75,41) ; v1(3.25,38) P18.6@5.225,38 ; v1(5.2,31.3) 5.225,31.325 P18.12@5.225,32 ; C29.1@7.65,17.785 v1(7.65,18.5) ; v1(7.95,34.5) 7.95,34.65 8.56,35.26 J10.9@8.868,35.26 ; SW1.1@8.4,31 v1(10.05,31) ; v1(8.85,63.7) 8.9,63.65 D6.K@8.9,62.8 ; D5.K@11.5,62.8 D4.K@14.1,62.8 13.2,63.7 v1(13.1,63.7) ; v1(12.4,31) SW1.2@14.2,31 ; J11.3@13.332,52.63 J11.5@13.332,53.9 14.64,53.9 14.65,53.91 14.65,53.928 15.322,54.6 v1(15.4,54.6) ; J11.9@13.332,56.44 15.01,56.44 v1(15.35,56.1) ; v1(18.1,63.95) 18.375,63.95 18.625,64.2 ; v1(21.9,63.95) 22.25,63.95 22.375,64.075 J19.10@22.375,65.2 ; v1(24.25,31.25) C58.1@24.915,31.25 ; v1(24.25,34) C59.1@24.915,34 ; C45.1@24.915,35.5 v1(24.25,36) C42.1@24.915,36.625 ; v1(25.75,63.95) 25.975,63.95 26.125,64.1 J19.7@26.125,65.2 ; v1(25.9,41.65) 26.425,41.65 C28.1@26.625,41.85 ; v1(26.9,39.25) 27.125,39.025 C44.1@27.125,38.585 ; v1(28.125,40.725) X1.4@28.125,41.675 ; v1(28.15,43.35) 28.63,43.35 C30.1@28.89,43.09 ; v1(29.85,66.85) 29.875,66.825 J19.4@29.875,65.2 ; C53.1@37.96,29.71 v1(38.5,30.25) ; C54.1@38.5,32.125 v1(39,32.125) ; C48.1@38.71,34.5 v1(39.5,34.5) ; U1.D4@53.5,56.5 v1(54.3,56.5) ; v1(54.7,68.25) 54.7,70.15 54.975,70.425 P20.15@55.7,70.425 ; v1(57.65,67.85) 57.9,68.1 58.424,68.1 58.7,67.824 P20.12@58.7,66.775 ; v1(61.7,68.85) P20.9@61.7,70.425 ; v1(64.7,65.4) P20.6@64.7,66.775
  Top Layer w0.5: v1(94.4,11.25) 94.35,11.3 D1.K@94.35,12.7 94.45,12.6 v1(94.45,14.15)
  Bottom Layer w0.15: v1(6.7,36.95) 8.1,38.35 10.885,38.35 CAD1.3@11.535,37.7 ; v1(70.95,29.85) 71.51,30.41 C118.1@71.51,30.9 ; v1(71.75,29.75) 72.52,30.52 R20.1@72.52,30.9
  Bottom Layer w0.2: R46.1@16.125,2.48 v1(16.125,3.25) ; v1(16.125,4.75) R54.2@16.125,5.52 ; C33.2@17.25,2.46 v1(17.25,3.25) ; v1(17.375,4.75) R56.2@17.375,5.52 ; J33.1@39.75,66.8 v1(39.75,67.75) ; J33.10@44.25,66.8 v1(44.25,68.2) ; U12.4@45.155,28.825 45.155,27.395 45.5,27.05 v1(45.7,27.05) ; J33.17@47.75,66.8 v1(47.75,67.75) ; R42.1@64.15,39.87 64.27,39.75 v1(64.875,39.75) ; R43.1@64.15,42.88 64.77,43.5 v1(64.875,43.5) ; C111.1@70.75,52.55 70.88,52.68 C112.1@72.3,52.68 72.61,52.99 C113.1@73.45,52.99 73.74,52.7 75.3,52.7 75.35,52.75 ; U23.1@75.35,53.3 75.35,52.75 ; C6.1@75.5,22.96 75.44,22.96 v1(74.9,23.5) 75.44,24.04 C5.1@75.5,24.04 ; C109.1@78,51.38 77.22,51.38 76.15,52.45 U23.12@76.15,52.85 76.05,52.75 75.35,52.75 ; v1(86.35,47.05) 86.49,46.91 J14.14@86.49,46.61 ; J14.13@86.49,32.39 v1(86.49,33) ; J14.5@91.41,35.12 92.07,35.12 v1(92.1,35.15) ; v1(92.15,47.05) 92.35,46.85 J14.15@92.35,46.61 ; v1(92.3,31.9) 92.35,31.95 J14.12@92.35,32.39 ; R14.1@93.84,22.55 94.15,22.24 v1(94.15,21.95)
  Bottom Layer w0.25: CAD2.3@11.935,53.8 13.2,53.8 14,54.6 v1(15.4,54.6) ; v1(24.25,31.25) R71.1@24.895,31.25 24.915,31.23 C57.1@24.915,30.125 ; R73.1@24.895,33.5 v1(24.25,34) R74.1@24.895,34.625 ; C68.1@25.625,18.79 26.263,19.428 v1(26.263,19.671) 26.164,19.671 C65.2@25.625,20.21 ; U14.6@25.75,21.81 v1(25.75,23) ; C65.2@25.76,20.425 U14.6@25.76,21.8 ; v1(26.4,52.9) C24.1@26.4,53.54 ; C70.1@28.085,20.125 C69.1@28.085,18.75 v1(28.875,18.75) ; U20.3@30.575,24.275 30.6,24.25 v1(31.25,24.25) ; v1(30.75,25.75) C73.1@30.75,26.415 ; v1(31.625,25.75) C78.1@31.625,26.415 ; X2.4@33.1,41.05 33.44,40.71 C64.2@34.5,40.71 34.5,41.4 35.2,42.1 v1(35.8,42.1) ; v1@33.365,28.375 33.365,29.94 U13.11@33.375,29.95 ; v1(33.85,51.9) 33.86,51.91 Q5.S@34.35,51.91 ; C79.1@34.61,38.05 34.66,38.1 v1(35.6,38.1) ; v1(34.625,25.75) C74.1@34.625,26.415 ; D10.1@35.625,6.925 v1(35.625,7.5) ; v1(36.35,25.75) 36.375,25.775 C49.1@36.375,26.415 ; C67.1@38.25,24.21 v1(38.25,25.05) 38.785,25.05 C66.1@39.375,24.46 ; v1(39,43.3) R145.1@39,43.82 ; v1@43.5,45.35 v1(43.45,45.4) 44.28,45.4 R134.2@44.85,44.83 ; v1(47.5,39.2) 48.15,38.55 C39.1@49.09,38.55 ; v1(47.9,17.55) 48.125,17.325 R89.1@48.125,16.605 ; v1(48.2,3.77) C83.1@48.2,4.415 ; v1(48.5,26.5) R59.2@49.02,26.5 49.02,25.49 R27.1@48.88,25.35 ; C38.1@50.625,15.665 50.625,15.425 v1(51,15.05) ; v1(50.85,45.2) 51.04,45.01 C37.1@51.04,44.5 ; v1(51,41.85) 51.04,41.89 C41.1@51.04,42.5 ; v1(51.875,6.525) U16.14@51.875,7.85 51.875,13.55 U16.25@51.875,13.65 v1(51.875,14.65) ; v1(52.7,23) J12.50@54.4,23 ; v1(53,27.15) 53.15,27 J12.40@54.4,27 ; C80.1@53.35,4.65 C80.1@53.35,4.75 53.35,5.875 v1(53.375,5.9) 53.375,7.75 U16.28@53.375,13.65 v1(53.375,14.65) ; J12.34@54.4,29.4 55.75,29.4 v1(56.05,29.1) ; J12.26@54.4,32.6 56.275,32.6 v1(56.375,32.5) ; J12.18@54.4,35.8 v1(55.95,35.8) ; v1(54.5,65.9) J21.1@54.5,66.8 ; v1(54.875,6.525) 54.875,7.75 U16.31@54.875,13.55 ; U16.31@54.875,13.65 v1(54.875,14.65) ; v1(56.375,5.9) U16.5@56.375,7.85 v1(56.375,10.625) 56.375,13.55 U16.34@56.375,13.65 v1(56.375,14.65) ; v1(57.375,14.65) U16.36@57.375,13.65 57.375,7.75 v1(57.375,5.9) 57.375,5.19 C81.1@57.415,5.15 ; R57.2@58.88,16.7 58.88,15.62 C84.1@58.86,15.6 58.86,14.54 v1(59.35,14.05) ; v1(59.35,55.35) 59.4,55.3 C36.2@59.4,53.65 ; v1(60.55,28.7) 60.85,29 J12.35@62.6,29 ; v1(61.1,25.75) 61.15,25.8 J12.43@62.6,25.8 ; v1(61.2,27.55) 61.2,27.8 61.6,28.2 J12.37@62.6,28.2 ; v1(61.25,31.4) J12.29@62.6,31.4 ; v1(61.25,32.2) J12.27@62.6,32.2 ; v1(61.25,34.75) 61.4,34.6 J12.21@62.6,34.6 ; v1(61.35,40.2) J12.15@62.6,40.2 ; v1(61.35,42.65) 61.4,42.6 J12.9@62.6,42.6 ; v1(64.25,26.5) C95.1@64.79,26.5 ; v1(64.35,24.6) 64.45,24.5 C89.1@65.04,24.5 ; v1(67,65.45) J21.26@67,66.8 ; J21.28@68,66.8 68,65.9 68.25,65.65 v1(68.25,65.45) ; R37.1@70.42,50.4 70.42,50.055 v1(70.85,49.625) ; U17.31@70.75,28.95 70.75,29.75 70.85,29.85 v1(70.95,29.85) ; U17.32@71.25,28.95 71.25,29.25 v1(71.75,29.75) ; U17.3@71.95,27.25 v1(72.75,27.25) ; U17.1@71.95,28.25 72.25,28.25 v1(72.625,28.625) ; J21.36@72,66.8 v1(72,67.75) ; C90.1@72.625,20.165 72.71,20.165 v1(73.25,19.625) ; R29.2@73.28,50.4 73.28,49.695 v1(73.35,49.625) ; v1@73.7,14.425 J7.9@73.7,15.55 ; L27.1@75.15,29.9 75.85,29.9 v1(76.2,30.25) 76.69,30.25 C96.1@76.75,30.31 ; C7.1@75.5,18.96 v1(75.5,19.5) ; v1(78,3.25) J7.6@78,5.05 v1(78,6.625) ; v1@78.875,17 78.875,16.075 J7.10@79.4,15.55 ; U2.2@79.6,21.5 v1(80.45,21.5) ; U6.3@79.6,23.85 v1(80.5,23.85) ; C4.1@81.96,24.5 v1(82.7,24.5) ; R28.2@82.63,50.35 82.63,51.08 v1(83.3,51.75) ; Q4.S@84.09,30.4 84.09,29.76 v1(84.3,29.55) ; v1(84.15,25.4) 84.17,25.42 R19.2@84.17,26 ; C99.1@85.5,60.04 86.24,60.04 v1(86.25,60.05) ; v1(86.7,28.3) 86.9,28.1 R17.2@86.9,27.78 ; D2.A@87.67,24.25 v1(88.4,24.25) 88.6,24.25 89.1,23.75 C3.1@89.61,23.75 ; U18.2@88.675,59.74 89.69,59.74 v1(89.7,59.75) ; v1(98.7,31.85) J14.11@98.7,32.55 ; v1(98.7,45.75) J14.16@98.7,46.45
  Bottom Layer w0.3: C105.1@5.2,42.91 v1(5.2,43.7) ; v1(22.55,49.65) 22.8,49.9 C101.1@22.8,50.44 ; R146.1@23.73,36 v1(24.25,36) ; C26.1@28.2,59.19 28.4,58.99 v1(28.4,57.8) ; C25.1@36.85,56.31 v1(36.85,57) ; C27.1@36.9,61.19 37.225,60.865 v1(37.225,60.525) ; C76.1@37.21,37 37.7,37 v1(37.8,37.1) ; R70.1@37.23,38.125 37.655,38.55 v1(38.05,38.55) ; C75.1@38.335,32.5 38.625,32.5 v1(39,32.125) ; Q2.S@42.625,19.44 v1(42.625,20.346) ; U7.5@43.3,56.9 43.55,57.15 U7.2@43.55,57.71 ; U12.6@43.885,23.425 43.885,21.675 C62.1@43.585,21.375 44.125,21.375 v1(44.15,21.4) ; C10.1@43.96,58.95 44.6,58.95 v1(44.7,58.85) C8.1@44.7,60.15 ; C11.1@44.65,57.56 44.65,58.1 v1(44.75,58.2) ; C9.2@45.75,61.85 45.75,63.05 v1(45.8,63.1) ; v1(46,36.95) C35.2@47.15,36.95 ; C34.2@48.4,18.5 49.1,18.5 v1(49.75,19.15) ; v1(49.3,17.4) 49.35,17.4 49.375,17.375 C85.1@49.375,16.585 ; v1(52.8,44.5) 52.9,44.6 J12.4@54.4,44.6 ; R138.1@73.3,57.53 73.3,59.05 73.75,59.5 75.8,59.5 ; C110.1@75.75,57.71 75.75,59.45 75.8,59.5 ; R144.1@77.3,58.65 77.3,59.4 77.4,59.5 ; C109.1@78,51.38 80.98,51.38 81.8,52.2 82.85,52.2 83.4,52.75 83.4,57.9 81.8,59.5 77.4,59.5 ; U4.2@79.6,18.5 v1(80.55,18.5) ; C100.1@86,54.11 86.54,54.11 v1(86.55,54.1) ; U19.2@87.8,51.865 88.785,51.865 v1(88.8,51.85) ; 75.8,59.5 77.4,59.5
  Bottom Layer w0.4: v1(13.6,66.45) 13.625,66.425 J31.4@13.625,65.2 ; 17.375,64.2 17.375,64.175 v1(17.6,63.95) ; v1(21.1,63.95) 21.125,63.975 J31.10@21.125,65.2 ; v1(22.7,53.55) v1@22.71,53.54 ; R84.1@24.03,47 v1(24.6,47) ; v1(24.25,32.625) 24.5,32.375 C77.1@24.915,32.375 ; J31.13@24.875,65.2 24.875,66.525 v1(24.9,66.55) ; C60.1@27.24,39.9 26.9,39.56 v1(26.9,39.25) 26.9,38.81 C72.1@27.125,38.585 27.14,38.6 C61.1@28.24,38.6 ; v1(28.125,40.725) 28.575,40.725 29.135,40.165 C63.2@29.5,40.165 29.5,39.95 30,39.45 X2.2@30.9,39.45 ; v1(46.65,42.55) 46.7,42.5 C40.1@47.6,42.5 ; v1(56.6,56.45) R5.1@57.47,56.45 ; v1(85.15,13.65) FIL1.2@85.55,14.05 ; FIL1.2@85.55,15.2 FIL1.2@85.55,14.05 ; v1(85.8,13.65) 85.55,13.9 FIL1.2@85.55,14.05
  other v1: 6,1.125 7.25,1.125 84.5,1.125 87.625,1.125 88.875,1.125 90,1.625 90.875,2.5 92.625,4.25 93.5,5.125 94.35,5.35 99.275,6.225 95.1,7.45 99.275,7.475 0.725,7.625 96.9,7.8 99.275,8.725 0.725,9 34,9.625 99.275,9.975 0.725,10.25 14.65,10.65 71.725,10.85 99.275,11.225 20.775,11.575 0.725,11.625 35.05,11.7 37,11.75 58.6,12.375 99.275,12.475 0.725,12.875 99.275,13.725 13.5,13.875 16.125,13.875 18.625,13.875 21.25,13.875 0.725,14.125 73.75,14.375 33.4,14.5 35.35,14.5 30,14.625 99.275,14.975 0.725,15.375 29.25,15.375 99.275,16.225 0.725,16.625 78.875,17.125 57.35,17.3 50.9,17.35 99.275,17.35 0.725,17.875 54.2,17.9 16.825,17.975 4.7,18.15 6.65,18.15 20.95,18.15 18.75,18.3 22.15,18.375 23.4,18.375 56.3,18.4 14.375,18.95 15.525,18.95 19.4,18.975 99.275,18.975 0.725,19.125 17.525,19.2 4.7,19.4 22.15,19.625 18.475,20.15 99.275,20.35 0.725,20.375 20.65,20.4 14.4,20.725 19.725,21.275 15.525,21.325 99.275,21.6 0.725,21.625 0.725,22.875 29.625,22.875 99.275,22.975 24.575,23.25 16.575,23.35 17.675,23.35 18.875,23.35 46.7,24 19.725,24.1 20.85,24.1 0.725,24.125 99.275,24.225 25.875,24.275 46.175,24.9 68.25,25.25 19.725,25.35 20.85,25.35 0.725,25.375 99.275,25.475 95.45,25.75 94.95,26.05 43.25,26.25 0.725,26.625 99.275,26.725 95.4,26.95 94.85,27.25 37.125,27.375 68.25,27.75 70.75,27.75 27.85,27.85 99.275,27.975 33.375,28.25 39.85,29.15 99.275,29.225 66.25,29.3 47.45,29.5 17,29.6 18.25,29.598 66.85,29.75 99.275,30.475 4.3,30.8 2.9,31.05 30.25,31.125 33.5,31.125 46.9,31.35 79.45,31.6 68.4,31.625 69.65,31.625 70.9,31.625 72.15,31.625 73.4,31.625 77.15,31.625 78.4,31.625 99.275,31.725 64.875,32.25 82.8,32.5 31.875,32.75 41.305,32.923 4.1,32.95 20,33.5 20.55,33.5 64.875,33.525 82.775,33.525 99.3,33.6 20,34.15 20.55,34.15 99.3,34.35 30.25,34.375 33.5,34.375 52.65,34.6 64.875,34.75 82.775,34.75 47.5,35.5 40.75,35.6 99.3,35.9 64.875,36 82.775,36 2.9,36.25 99.3,36.9 64.875,37.25 82.775,37.25 22,37.45 31.05,37.45 23.45,38.4 99.3,38.45 64.875,38.5 82.775,38.5 18.25,38.95 99.3,39.35 82.775,39.75 20.9,39.95 57.55,40.4 46.25,40.6 22.3,40.65 52.6,40.7 99.3,40.95 16.45,41 64.875,41 82.775,41 17.45,41.75 99.3,41.9 64.875,42.25 82.775,42.25 57.6,42.35 52.65,42.4 18.35,43 82.775,43.5 99.275,43.875 64.875,44.75 82.775,44.75 99.275,45.25 14.15,45.55 64.875,46 82.775,46 0.65,46.775 52.472,46.873 46.15,46.9 15,47.05 64.875,47.25 82.775,47.25 99.275,47.875 46.15,48.1 0.675,48.15 64.875,48.5 84.35,48.55 99.275,49.125 0.65,49.4 64.9,49.5 83.6,49.5 68.35,49.625 69.6,49.625 72.1,49.625 74.6,49.625 75.85,49.625 77.1,49.625 99.275,50.375 0.65,50.775 99.275,51.625 74.45,51.7 75.05,51.7 75.7,51.7 76.15,52 76.7,52 0.65,52.025 56.6,52.05 99.275,52.875 62.4,53 0.65,53.275 23.65,53.45 24.3,53.45 54.45,53.5 65.35,53.5 47.5,53.55 99.275,54.125 60.5,54.5 0.65,54.525 82.65,54.55 99.275,55.375 69.55,55.55 23.3,55.75 0.65,55.775 69.05,55.8 22.95,56.1 82.65,56.45 23.3,56.5 78.5,56.55 99.275,56.625 22.95,56.9 0.65,57.025 99.275,57.875 0.65,58.275 78.65,58.5 99.275,59.125 65.85,59.5 0.65,59.525 54.5,59.55 54.5,60.3 99.275,60.375 72.45,60.7 0.65,60.775 22.25,60.85 66.35,60.95 31.95,61.05 16.2,61.075 20.175,61.1 26.65,61.1 27.85,61.1 18.25,61.15 24.25,61.15 14.865,61.2 11.616,61.202 25.9,61.25 75.6,61.45 62.4,61.5 74.1,61.5 81.4,61.5 99.275,61.625 32.75,61.65 67.55,61.7 84.75,61.7 0.675,62.05 76.7,62.05 99.275,62.875 0.675,63.25 99.275,64.125 0.65,64.525 64.1,64.9 62.35,65.2 99.275,65.375 0.65,65.775 99.275,66.5 5.9,71.2 8.9,71.225 76.925,71.225 78.3,71.225 79.55,71.225 80.925,71.225 82.175,71.225 83.425,71.225 84.675,71.225 85.925,71.225 87.175,71.225 88.425,71.225 89.675,71.225 90.925,71.225 92.175,71.225 93.425,71.225 94.675,71.225 9.925,71.25 11.175,71.25 12.425,71.25 13.675,71.25 14.925,71.25 16.175,71.25 17.425,71.25 18.675,71.25 19.925,71.25 21.175,71.25 22.425,71.25 23.675,71.25 24.925,71.25 26.175,71.25 27.425,71.25 28.55,71.25
HDMI_CEC_IN: R88.2 U1.H2 U16.16 | length 55.3
  Top Layer w0.125: v1(48.75,48.875) U1.H2@49.5,48.5
  Layer 5 w0.125: v1(48.75,48.875) 49.413,48.212 52.524,48.212 52.599,48.288 53.421,48.288 54.2,47.508 54.2,25.6 57.375,22.425 57.375,19.532 58.4,18.507 58.4,14.35 50.875,6.825 v1(50.875,6.602)
  Bottom Layer w0.125: R88.2@50.875,5.27 R88.2@50.875,5.355 v1(50.875,6.602) U16.16@50.875,7.85
HDMI_CLK_N: L43.4 U1.E8 | length 49.8
  Top Layer w0.104: v1(60.5,53.875) 60.748,53.628 61.375,53.628 61.5,53.753 U1.E8@61.5,54.5
  Layer 8 w0.093: v1(51.5,17.35) 51.75,17.6 51.75,17.8 52.15,18.2 52.941,18.2 53.391,18.649 ; 53.141,18.4 53.391,18.649 ; 57.499,49.01 57.499,49.59 ; 57.5,49.009 57.5,48.8 56.625,47.925 56.625,44.25 58.6,42.275 58.6,40.775 57.7,39.874 57.7,28.626 58.451,27.875 59.125,27.875 59.5,27.5 59.5,20.799 57.851,19.15 55.561,19.15 55.064,18.653 53.395,18.653 53.391,18.649 ; 57.5,49.591 57.5,50.75 59.325,52.575 59.325,53.099 59.876,53.65 60.275,53.65 v1(60.5,53.875)
  Bottom Layer w0.104: v1(51.5,17.35) 51.695,17.155 51.695,16.82 L43.4@51.575,16.7
HDMI_CLK_P: L43.1 U1.F8 | length 49.3
  Top Layer w0.104: v1(60.5,53.125) 60.748,53.372 61.35,53.372 61.5,53.222 U1.F8@61.5,52.5
  Layer 8 w0.093: v1(52.25,17.35) 52.05,17.55 52.05,17.676 52.274,17.9 53.065,17.9 53.515,18.349 ; 53.353,18.188 53.515,18.349 ; 57.799,49.134 57.799,49.466 ; 57.8,49.134 57.8,48.676 56.925,47.801 56.925,44.374 58.9,42.399 58.9,40.65 58,39.75 58,28.75 58.575,28.175 59.325,28.175 59.8,27.7 59.8,20.675 57.975,18.85 55.685,18.85 55.188,18.353 53.519,18.353 53.515,18.349 ; 57.8,49.466 57.8,50.626 59.625,52.451 59.625,52.975 60,53.35 60.275,53.35 v1(60.5,53.125)
  Bottom Layer w0.104: L43.1@52.125,16.7 51.95,16.875 51.95,17.15 52.15,17.35 v1(52.25,17.35)
HDMI_D0_N: L41.4 U1.A9 | length 57.5
  Top Layer w0.104: v1(62.875,61.875) 63.122,61.628 63.375,61.628 63.5,61.753 U1.A9@63.5,62.5
  Layer 3 w0.093: v1(53,17.35) 53.2,17.15 53.2,16.651 53.801,16.05 58.524,16.05 59.625,17.151 59.625,18.326 62.375,21.076 62.375,49.45 63.712,50.787 63.712,56.788 64.05,57.126 64.05,61.224 63.624,61.65 63.1,61.65 v1(62.875,61.875)
  Bottom Layer w0.104: v1(53,17.35) 53.075,17.275 L41.4@53.075,16.7
HDMI_D0_P: L41.1 U1.B9 | length 57.1
  Top Layer w0.104: v1(62.875,61.125) 63.123,61.373 63.378,61.373 63.5,61.25 U1.B9@63.5,60.5
  Layer 3 w0.093: v1(53.7,17.35) 53.5,17.15 53.5,16.775 53.925,16.35 54.165,16.35 ccw(c54.165,16.485) 54.301,16.485 54.301,16.615 cw(c54.436,16.615) 54.436,16.75 54.466,16.75 cw(c54.466,16.615) 54.602,16.615 54.602,16.485 ccw(c54.737,16.485) 54.737,16.35 54.767,16.35 ccw(c54.767,16.485) 54.903,16.485 54.903,16.615 cw(c55.038,16.615) 55.038,16.75 55.068,16.75 cw(c55.068,16.615) 55.204,16.615 55.204,16.485 ccw(c55.339,16.485) 55.339,16.35 58.4,16.35 59.325,17.275 59.325,18.45 62.075,21.2 62.075,49.574 63.412,50.911 63.412,56.912 63.75,57.25 63.75,61.1 63.5,61.35 63.1,61.35 v1(62.875,61.125)
  Bottom Layer w0.104: L41.1@53.625,16.7 53.625,17.275 v1(53.7,17.35)
HDMI_D1_N: L39.4 U1.B8 | length 50.9
  Top Layer w0.104: v1(60.75,59.875) 60.998,59.628 61.375,59.628 61.5,59.753 U1.B8@61.5,60.5
  Layer 3 w0.093: v1(54.5,17.35) 54.7,17.55 54.7,17.974 56.076,19.35 58.05,19.35 59.625,20.925 59.625,42.425 58.662,43.388 58.662,45.036 59.55,45.924 59.55,49.476 58.25,50.776 58.25,57.899 60.001,59.65 60.525,59.65 v1(60.75,59.875)
  Bottom Layer w0.104: v1@54.55,17.35 54.745,17.155 54.745,16.82 L39.4@54.625,16.7
HDMI_D1_P: L39.1 U1.C8 | length 50.5
  Top Layer w0.104: v1(60.75,59.125) 60.998,59.372 61.375,59.372 61.5,59.247 U1.C8@61.5,58.5
  Layer 3 w0.093: v1(55.25,17.35) 55.2,17.35 55,17.55 55,17.85 56.2,19.05 58.174,19.05 59.925,20.801 59.925,42.549 58.962,43.512 58.962,44.912 59.85,45.8 59.85,49.6 58.55,50.9 58.55,57.775 60.125,59.35 60.525,59.35 v1(60.75,59.125)
  Bottom Layer w0.104: L39.1@55.175,16.7 55,16.875 55,17.15 v1@55.2,17.35
HDMI_D2_N: L37.4 U1.F7 | length 43.2
  Top Layer w0.104: U1.F7@59.5,52.5 59.5,51.752 59.625,51.628 60.253,51.628 v1(60.5,51.875)
  Layer 8 w0.093: v1(56,17.35) 56.225,17.575 56.225,17.749 56.526,18.05 58.751,18.05 61.75,21.049 61.75,28.066 60.716,29.101 60.713,29.101 60.713,29.103 59.6,30.216 59.6,42.774 60.2,43.374 60.2,48 59.375,48.825 59.375,51.299 59.726,51.65 60.275,51.65 v1(60.5,51.875)
  Bottom Layer w0.104: v1@56.05,17.35 56.245,17.155 56.245,16.82 L37.4@56.125,16.7
HDMI_D2_P: L37.1 U1.G7 | length 42.7
  Top Layer w0.104: U1.G7@59.5,50.5 59.5,51.248 59.625,51.373 60.253,51.373 v1(60.5,51.125)
  Layer 8 w0.093: v1(56.75,17.35) 56.525,17.575 56.525,17.625 56.65,17.75 58.875,17.75 62.05,20.925 62.05,28.129 62.05,28.191 59.9,30.341 59.9,42.65 60.5,43.25 60.5,48.124 59.675,48.949 59.675,51.175 59.85,51.35 60.275,51.35 v1(60.5,51.125)
  Bottom Layer w0.104: L37.1@56.675,16.7 56.5,16.875 56.5,17.15 v1@56.7,17.35
HDMI_DDC_SCL: P1.15 R87.1 U16.22 | length 15.7
  Top Layer w0.125: P1.15@49.875,8.5 v1(49.875,10.25) 50.375,10.75 50.375,12.625 51.737,13.987 55.747,13.987 56.485,13.25 R87.1@57.27,13.25
  Bottom Layer w0.125: v1(49.875,10.25) 50.375,10.75 U16.22@50.375,13.65
HDMI_DDC_SDA: P1.16 R85.1 U16.21 | length 6.4
  Top Layer w0.125: R85.1@48.855,12.25 49.375,12.25 49.5,12.375 v1(49.875,12.375) 49.875,11.125 49.375,10.625 P1.16@49.375,8.5
  Bottom Layer w0.125: v1(49.875,12.375) U16.21@49.875,13.65
HDMI_FIL_CLK_N: L43.3 P1.12 U16.15 U16.24 | length 12.1
  Top Layer w0.122: v1(51.375,6) 51.4,6.025 P1.12@51.4,8.6
  Bottom Layer w0.104: U16.24@51.375,13.65 51.375,14.733 51.575,14.933 L43.3@51.575,15.4
  Bottom Layer w0.122: v1(51.375,6) U16.15@51.375,7.85 U16.24@51.375,13.65
HDMI_FIL_CLK_P: L43.2 P1.10 U16.13 U16.26 | length 12.1
  Top Layer w0.122: v1(52.375,6) 52.4,6.025 P1.10@52.4,8.6
  Bottom Layer w0.104: L43.2@52.125,15.4 52.125,14.983 52.375,14.733 U16.26@52.375,13.65
  Bottom Layer w0.122: v1(52.375,6) U16.13@52.375,7.85 U16.26@52.375,13.65
HDMI_FIL_D0_N: L41.3 P1.9 U16.12 U16.27 | length 10.7
  Top Layer w0.122: v1(52.875,6.625) P1.9@52.875,8.5
  Bottom Layer w0.104: U16.27@52.875,13.65 52.875,14.825 53.075,15.025 L41.3@53.075,15.4
  Bottom Layer w0.122: v1(52.875,6.625) U16.12@52.875,7.85 U16.27@52.875,13.65
HDMI_FIL_D0_P: L41.2 P1.7 U16.10 U16.29 | length 10.8
  Top Layer w0.122: v1(53.875,6.625) P1.7@53.875,8.5
  Bottom Layer w0.104: L41.2@53.625,15.4 53.625,14.983 53.875,14.733 U16.29@53.875,13.65
  Bottom Layer w0.122: v1(53.875,6.625) U16.10@53.875,7.85 U16.29@53.875,13.65
HDMI_FIL_D1_N: L39.3 P1.6 U16.9 U16.30 | length 12
  Top Layer w0.122: v1(54.375,6) P1.6@54.375,8.5
  Bottom Layer w0.104: U16.30@54.375,13.65 54.375,14.825 54.575,15.025 L39.3@54.575,15.4
  Bottom Layer w0.122: v1(54.375,6) U16.9@54.375,7.85 U16.30@54.375,13.65
HDMI_FIL_D1_P: L39.2 P1.4 U16.7 U16.32 | length 12
  Top Layer w0.122: v1(55.375,6) P1.4@55.375,8.5
  Bottom Layer w0.104: L39.2@55.125,15.4 55.125,14.983 55.375,14.733 U16.32@55.375,13.65
  Bottom Layer w0.122: v1(55.375,6) U16.7@55.375,7.85 U16.32@55.375,13.65
HDMI_FIL_D2_N: L37.3 P1.3 U16.6 U16.33 | length 10.8
  Top Layer w0.122: v1(55.875,6.625) P1.3@55.875,8.5
  Bottom Layer w0.104: U16.33@55.875,13.65 55.875,14.733 56.125,14.983 L37.3@56.125,15.4
  Bottom Layer w0.122: v1(55.875,6.625) U16.6@55.875,7.85 U16.33@55.875,13.65
HDMI_FIL_D2_P: L37.2 P1.1 U16.4 U16.35 | length 10.7
  Top Layer w0.122: v1(56.875,6.625) P1.1@56.875,8.5
  Bottom Layer w0.104: L37.2@56.675,15.4 56.675,14.975 56.875,14.775 U16.35@56.875,13.65
  Bottom Layer w0.122: v1(56.875,6.625) U16.4@56.875,7.85 U16.35@56.875,13.65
